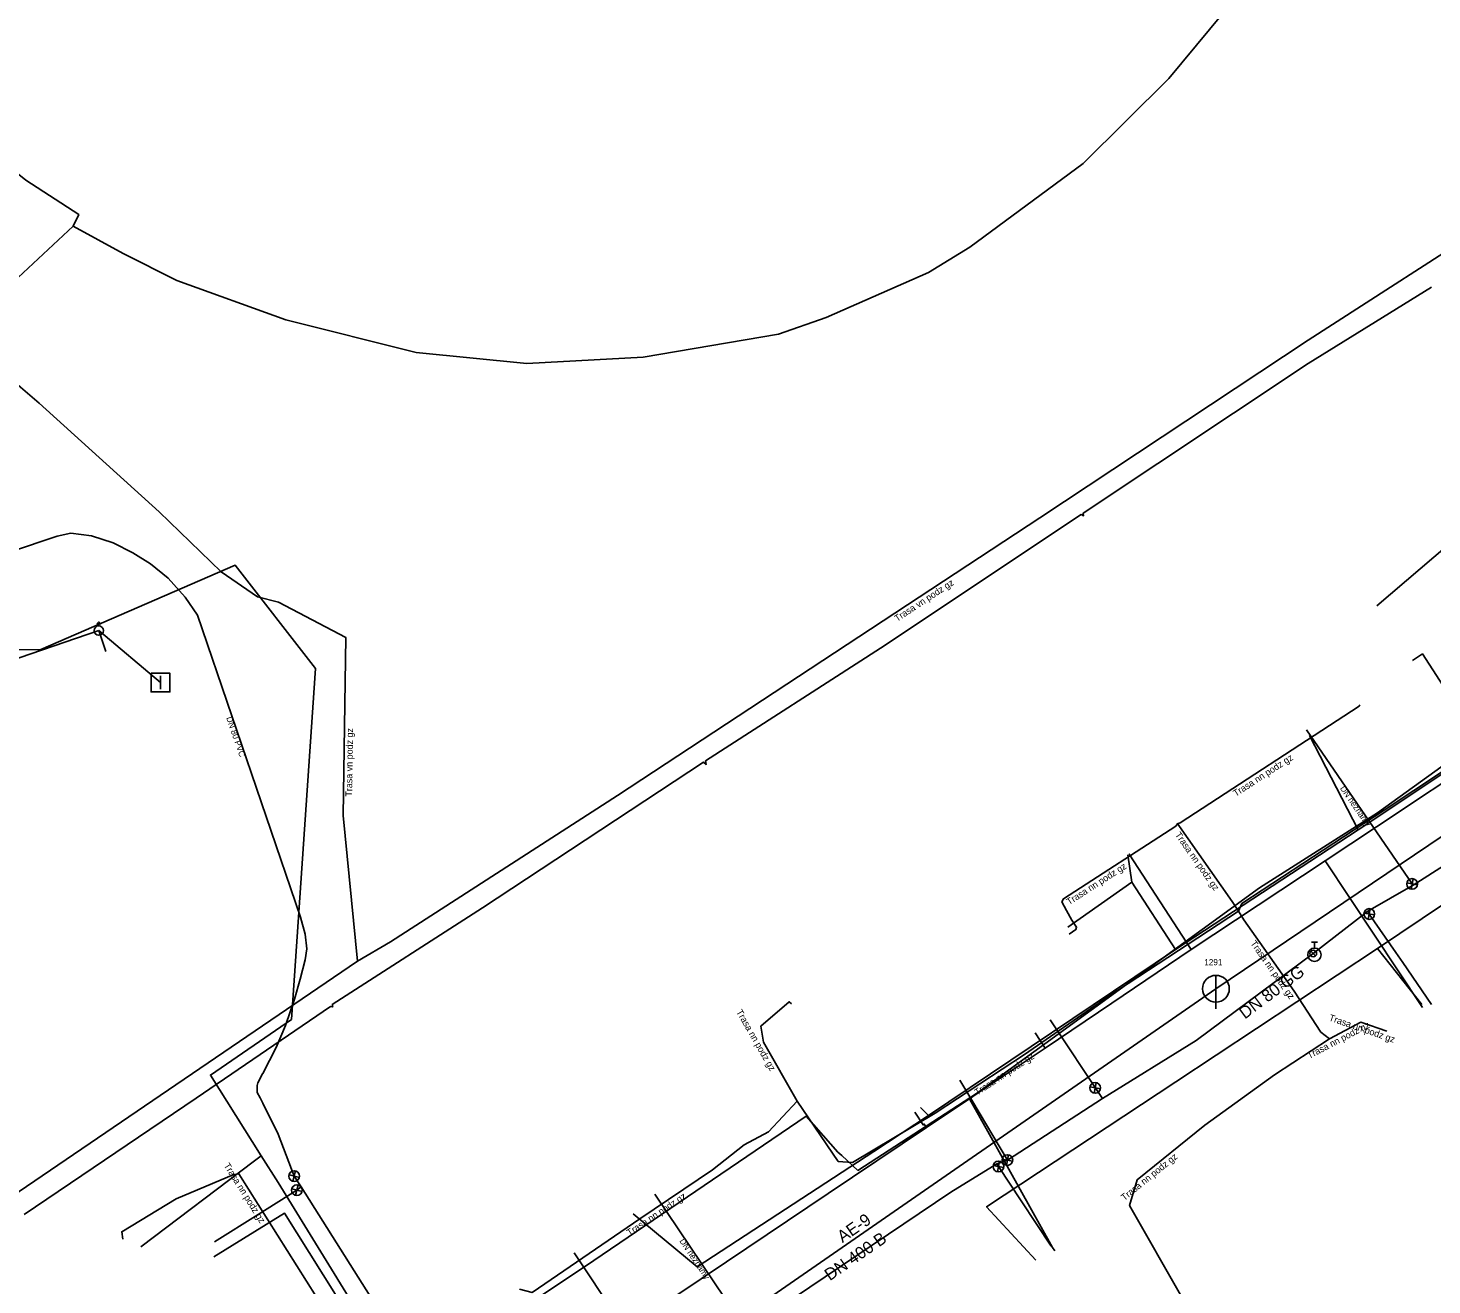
# Model space of a CAD drawing. Extents: x -493753 to -49291, y -1127285 to -112662.
# Drawn here: x -493093.4 to -492988.4, y -1126972.9 to -1126878.9 of the extents above; entities that cross this region are included whole.
import ezdxf

# ---------------------------------------------------------------- set-up
doc = ezdxf.new("R2010")
doc.units = 0
for name, color, linetype in [('Vrstva 1', 7, 'Continuous'), ('Vrstva 15', 7, 'Continuous'), ('Vrstva 17', 7, 'Continuous'), ('Vrstva 19', 7, 'Continuous'), ('Vrstva 20', 7, 'Continuous'), ('Vrstva 22', 7, 'Continuous'), ('Vrstva 24', 7, 'Continuous'), ('Vrstva 25', 7, 'Continuous'), ('Vrstva 26', 7, 'Continuous'), ('Vrstva 36', 7, 'Continuous'), ('Vrstva 39', 7, 'Continuous'), ('Vrstva 5', 7, 'Continuous'), ('Vrstva 6', 7, 'Continuous'), ('Vrstva 9', 7, 'Continuous')]:
    doc.layers.add(name, color=color, linetype=linetype)

# ---------------------------------------------------------------- blocks, each defined once
blk = doc.blocks.new('_UZAVE')
at = {"layer": 'Vrstva 1'}
for p, q in [((-0.035, -0.035), (0.035, 0.035)), ((0.035, -0.035), (-0.035, 0.035))]:
    blk.add_line(p, q, dxfattribs=at)
for radius in [0.05, 0.0025]:
    blk.add_circle((0, 0), radius, dxfattribs=at)
blk = doc.blocks.new('_UZAV0')
at = {"layer": 'Vrstva 1'}
for p, q in [((-0.035, -0.035), (0.035, 0.035)), ((0.035, -0.035), (-0.035, 0.035))]:
    blk.add_line(p, q, dxfattribs=at)
for radius in [0.05, 0.0025]:
    blk.add_circle((0, 0), radius, dxfattribs=at)
blk = doc.blocks.new('_HYDRA')
at = {"layer": 'Vrstva 1'}
for p, q in [((-0.0225, 0.095), (0.0225, 0.095)), ((0, 0.095), (0, 0.05))]:
    blk.add_line(p, q, dxfattribs=at)
blk.add_circle((0, 0), 0.05, dxfattribs=at)
blk = doc.blocks.new('_VPUST')
at = {"layer": 'Vrstva 1'}
blk.add_line((0, 0.025), (0, -0.025), dxfattribs=at)
blk.add_lwpolyline([(-0.035, 0.035), (0.035, 0.035), (0.035, -0.035), (-0.035, -0.035), (-0.035, 0.035)], dxfattribs=at)
blk = doc.blocks.new('_SACHT')
at = {"layer": 'Vrstva 1'}
blk.add_line((0, 0.035), (0, 0.05), dxfattribs=at)
blk.add_lwpolyline([(-0.015, 0.05), (0, 0.065), (0.015, 0.05), (0.0025, 0.05)], close=True, dxfattribs=at)
blk.add_circle((0, 0), 0.035, dxfattribs=at)
blk = doc.blocks.new('_SACH0')
at = {"layer": 'Vrstva 1'}
blk.add_line((0, 0.05), (0, -0.075), dxfattribs=at)
blk.add_circle((0, 0), 0.05, dxfattribs=at)

msp = doc.modelspace()

# ---------------------------------------------------------------- linework, layer by layer
at = {"layer": 'Vrstva 1'}
for p, q in [((-492989.07, -1126952.14), (-492996.36, -1126941.15)), ((-493018.05, -1126954.04), (-493017.3, -1126955.17)), ((-493076.44, -1126963.61), (-493075.92, -1126963.23)), ((-493076.44, -1126963.61), (-493084.94, -1126970.04)), ((-493052.53, -1126970.5), (-493048.7, -1126976.24))]:
    msp.add_line(p, q, dxfattribs=at)
for points in [[(-493061.95, -1126984.36), (-493055.3, -1126980.28), (-493048.7, -1126976.24), (-493041.12, -1126971.16), (-493033.53, -1126966.06), (-493026.17, -1126961.12), (-493022.95, -1126958.96), (-493022.37, -1126958.57), (-493017.3, -1126955.17), (-493012.3, -1126951.82), (-493006.38, -1126947.79), (-492996.36, -1126941.15), (-492992.52, -1126938.61), (-492984.26, -1126933.14), (-492976.86, -1126928.19), (-492969.03, -1126922.96), (-492962.21, -1126918.4), (-492958.1, -1126915.7), (-492957.92, -1126915.58), (-492957.82, -1126915.51), (-492938.13, -1126902.44)], [(-493075.92, -1126963.23), (-493079.73, -1126957.19), (-493073.66, -1126953.03), (-493071.87, -1126926.77), (-493077.88, -1126919.03), (-493092.4, -1126925.36), (-493094.9, -1126925.37)], [(-492984.26, -1126933.14), (-492989.08, -1126925.68), (-492989.83, -1126926.17)], [(-493011, -1126940.66), (-493011, -1126940.66), (-493006.38, -1126947.79)], [(-493016.58, -1126970.35), (-493016.75, -1126970.1), (-493019.17, -1126965.75), (-493021.59, -1126961.41), (-493022.95, -1126958.96)], [(-493026.17, -1126961.12), (-493026.34, -1126960.86), (-493026.42, -1126960.92), (-493027.04, -1126959.97)], [(-493075.92, -1126963.23), (-493074.66, -1126965.23), (-493065.8, -1126979.63), (-493063.11, -1126982.37), (-493061.95, -1126984.36), (-493057.28, -1126992.38), (-493056.62, -1126993.03), (-493050.57, -1126989.11), (-493043.53, -1127000), (-493040.17, -1127005.19), (-493038.27, -1127007.88), (-493030.16, -1127020.23)]]:
    msp.add_lwpolyline(points, dxfattribs=at)
at = {"layer": 'Vrstva 15'}
for p, q in [((-493088.08, -1126923.94), (-493098.62, -1126927.55)), ((-493087.54, -1126925.49), (-493088.08, -1126923.94)), ((-493083.46, -1126927.83), (-493088.08, -1126923.94)), ((-493057.41, -1126987.33), (-493004.52, -1126950.73))]:
    msp.add_line(p, q, dxfattribs=at)
msp.add_lwpolyline([(-493004.52, -1126950.73), (-492947.09, -1126911.99), (-492946.12, -1126911.1), (-492945.07, -1126909.77), (-492944.31, -1126908.4), (-492943.77, -1126906.95), (-492943.45, -1126905.36), (-492943.45, -1126904.13), (-492943.48, -1126903.21), (-492943.66, -1126901.96), (-492944.03, -1126900.73), (-492944.65, -1126899.35)], dxfattribs=at)
at = {"layer": 'Vrstva 20'}
for p, q in [((-492997.24, -1126948.09), (-492997.15, -1126948.19)), ((-492990.54, -1126948.78), (-492991.07, -1126948.01)), ((-492988.4, -1126951.9), (-492990.54, -1126948.78)), ((-493016.93, -1126953.07), (-493013.01, -1126958.95)), ((-493023.68, -1126957.57), (-493022.78, -1126959.08)), ((-493022.78, -1126959.08), (-493020.12, -1126963.55)), ((-493039.64, -1126976.26), (-493046.48, -1126966.09)), ((-493016.84, -1126970), (-493019.09, -1126966.61)), ((-493079.41, -1126969.66), (-493076.16, -1126967.62))]:
    msp.add_line(p, q, dxfattribs=at)
for points in [[(-493058.35, -1126988.86), (-493024.34, -1126965.95), (-493020.92, -1126963.84), (-493020.12, -1126963.55), (-493013.01, -1126958.95), (-493005.99, -1126954.61), (-492997.24, -1126948.09), (-492993.15, -1126944.92), (-492989.76, -1126942.99), (-492970.31, -1126930.58), (-492962.98, -1126925.47), (-492940.62, -1126910.81)], [(-493075.82, -1126957.1), (-493075.8, -1126957.08), (-493074.82, -1126955.14), (-493074.12, -1126953.49), (-493073.43, -1126951.51), (-493073.01, -1126950.02), (-493072.63, -1126948.56), (-493072.52, -1126947.74), (-493072.63, -1126946.66), (-493072.99, -1126945.37), (-493080.69, -1126922.79), (-493081.62, -1126921.43), (-493082.89, -1126920.01), (-493084.22, -1126918.93), (-493085.52, -1126918.12), (-493087, -1126917.38), (-493088.61, -1126916.85), (-493090.16, -1126916.64), (-493091.18, -1126916.88), (-493101.84, -1126920.45)], [(-492989.76, -1126942.99), (-492989.85, -1126942.89), (-492997.74, -1126931.37)], [(-492991.07, -1126948.01), (-492993.05, -1126945.14), (-492993.15, -1126944.92)], [(-493073.46, -1126964.75), (-493074.67, -1126961.6), (-493075.81, -1126959.29), (-493076.01, -1126958.9), (-493076.22, -1126958.49), (-493076.22, -1126958.22), (-493076.22, -1126957.98), (-493076.18, -1126957.76), (-493075.82, -1126957.1)], [(-493019.09, -1126966.61), (-493020.79, -1126964.03), (-493020.92, -1126963.84)], [(-493076.16, -1126967.62), (-493073.26, -1126965.8), (-493072.94, -1126965.55)], [(-493073.46, -1126964.75), (-493072.94, -1126965.55), (-493061.46, -1126983.73), (-493058.56, -1126988.53)]]:
    msp.add_lwpolyline(points, dxfattribs=at)
at = {"layer": 'Vrstva 25'}
msp.add_lwpolyline([(-493093.65, -1126967.62), (-493080.79, -1126958.93), (-493070.75, -1126952.05), (-493070.58, -1126952.09), (-493070.61, -1126951.91), (-493059.37, -1126944.69), (-493042.86, -1126933.79), (-493042.64, -1126933.95), (-493042.69, -1126933.69), (-493029.61, -1126925.25), (-493014.61, -1126915.26), (-493014.42, -1126915.34), (-493014.45, -1126915.14), (-492997.62, -1126903.95), (-492988.4, -1126898.25)], dxfattribs=at)
at = {"layer": 'Vrstva 26'}
for p, q in [((-492981.99, -1126930.04), (-492992.44, -1126937.56)), ((-492992.44, -1126937.56), (-493001.26, -1126943.19)), ((-493001.26, -1126943.19), (-493022.43, -1126958.57)), ((-493022.43, -1126958.57), (-493031.3, -1126964.34)), ((-493035.18, -1126960.26), (-493051.68, -1126971.48)), ((-493032.79, -1126962.96), (-493035.18, -1126960.26)), ((-493032.51, -1126963.2), (-493032.79, -1126962.96)), ((-493031.3, -1126964.34), (-493032.51, -1126963.2)), ((-493051.68, -1126971.48), (-493058.82, -1126976.24))]:
    msp.add_line(p, q, dxfattribs=at)
at = {"layer": 'Vrstva 36'}
msp.add_line((-492992.48, -1126922.08), (-492940.32, -1126877.38), dxfattribs=at)
at = {"layer": 'Vrstva 39'}
for points in [[(-493090, -1126893.68), (-493089.57, -1126892.81), (-493093.54, -1126890.23), (-493099.22, -1126885.65), (-493103.09, -1126881.61), (-493106.9, -1126876.5), (-493108.16, -1126874.25), (-493116.88, -1126869.66), (-493120.13, -1126868.36), (-493123.78, -1126862.9), (-493134.35, -1126847.08), (-493133.69, -1126846.76)], [(-493090, -1126893.68), (-493086.25, -1126895.72), (-493082.24, -1126897.74), (-493074.08, -1126900.68), (-493064.34, -1126903.13), (-493056.07, -1126903.96), (-493047.37, -1126903.49), (-493037.25, -1126901.75), (-493033.68, -1126900.51), (-493026.03, -1126897.15), (-493022.93, -1126895.26), (-493014.44, -1126889), (-493008.05, -1126882.62), (-493001.95, -1126875.27), (-492996.75, -1126867.41), (-492993.05, -1126859.65), (-492992.38, -1126855.25)], [(-493090, -1126893.68), (-493096.37, -1126899.62), (-493101.76, -1126903.61)], [(-492993.87, -1126938.84), (-492974.65, -1126926.06)], [(-492992.43, -1126947.71), (-492964.03, -1126928.65)], [(-492993.87, -1126938.84), (-492997.51, -1126931.79)], [(-492993.87, -1126938.84), (-493001.76, -1126944)], [(-493010.82, -1126942.75), (-493011.12, -1126940.72)], [(-493010.82, -1126942.75), (-493015.6, -1126946.12)], [(-493010.82, -1126942.75), (-493007.55, -1126947.79)], [(-493001.76, -1126944), (-493007.55, -1126947.79)], [(-493026.01, -1126960.22), (-493007.55, -1126947.79)], [(-492992.43, -1126947.71), (-493007.51, -1126957.69), (-493021.67, -1126967.04), (-493017.98, -1126971.03)], [(-492992.43, -1126947.71), (-492989.11, -1126951.92)], [(-493026.01, -1126960.22), (-493030.11, -1126962.9)], [(-493026.01, -1126960.22), (-493026.62, -1126959.62)], [(-493030.11, -1126962.9), (-493043.33, -1126971.54), (-493048.1, -1126967.58)], [(-493061.83, -1126987.26), (-493074.18, -1126967.53), (-493079.47, -1126970.79)]]:
    msp.add_lwpolyline(points, dxfattribs=at)
at = {"layer": 'Vrstva 5'}
for points in [[(-492968.17, -1126921.47), (-492971.15, -1126923.45), (-492980.93, -1126930.07), (-492991.95, -1126937.37), (-493002.59, -1126944.36), (-493002.84, -1126944.94)], [(-493007.4, -1126938.39), (-493007.19, -1126938.31), (-492993.8, -1126929.59), (-492993.77, -1126929.48)], [(-493002.84, -1126944.94), (-493003.3, -1126944.21), (-493007.43, -1126938.34)], [(-493007.4, -1126938.39), (-493007.52, -1126938.57), (-493015.93, -1126944), (-493016.04, -1126944.23), (-493015.7, -1126944.87), (-493015.29, -1126945.6), (-493014.94, -1126946.12), (-493015, -1126946.31), (-493015.49, -1126946.64)], [(-493002.84, -1126944.94), (-493012.6, -1126951.34), (-493018.85, -1126955.65), (-493025.53, -1126960.04), (-493031.7, -1126963.73), (-493032.77, -1126963.66), (-493035.84, -1126959.14)], [(-493002.84, -1126944.94), (-493002.43, -1126945.57), (-492998.67, -1126950.91), (-492996.67, -1126953.97), (-492996.03, -1126954.47)], [(-493035.84, -1126959.14), (-493038.37, -1126954.73), (-493038.55, -1126953.53), (-493036.43, -1126951.7), (-493036.26, -1126951.87)], [(-492996.03, -1126954.47), (-492993.68, -1126953.24), (-492993.62, -1126953.26)], [(-492993.62, -1126953.26), (-492991.74, -1126953.91)], [(-492996.03, -1126954.47), (-493000.14, -1126957.18), (-493005.36, -1126960.95), (-493010.42, -1126965.02), (-493010.98, -1126966.94), (-493006.97, -1126973.98), (-493010.17, -1126976.1), (-493010.66, -1126976.42)], [(-493035.84, -1126959.14), (-493037.99, -1126961.44), (-493039.81, -1126962.4), (-493042.17, -1126964.29), (-493047.62, -1126967.95), (-493055.67, -1126973.45), (-493056.61, -1126973.22)], [(-493069.65, -1126977.21), (-493077.59, -1126964.57), (-493077.98, -1126964.63), (-493082.28, -1126966.46), (-493086.36, -1126968.91), (-493086.27, -1126969.46)]]:
    msp.add_lwpolyline(points, dxfattribs=at)
at = {"layer": 'Vrstva 6'}
for points in [[(-493068.72, -1126948.66), (-493066.27, -1126947.23), (-493049.28, -1126936.27), (-493017.68, -1126915.5), (-492997.61, -1126902.22), (-492983.13, -1126892.87)], [(-493140.51, -1126905.23), (-493137.38, -1126905), (-493133.66, -1126905.28), (-493127.75, -1126903.34), (-493119.32, -1126900.41), (-493106.15, -1126895.75), (-493104.83, -1126895.77), (-493102.66, -1126897.52), (-493100.78, -1126899.84), (-493097.27, -1126902.88), (-493092.53, -1126906.92), (-493083.56, -1126915.04), (-493078.92, -1126919.55), (-493076.21, -1126921.42)], [(-493068.72, -1126948.66), (-493069.8, -1126937.76), (-493069.61, -1126924.45), (-493074.64, -1126921.81), (-493076.21, -1126921.42)], [(-493208.79, -1127019.8), (-493206.9, -1127018.9), (-493181.87, -1127010.51), (-493157.66, -1127002.21), (-493137.92, -1126995.41), (-493124.01, -1126986.08), (-493102.33, -1126971.53), (-493068.72, -1126948.66)]]:
    msp.add_lwpolyline(points, dxfattribs=at)

# ---------------------------------------------------------------- block references
at = {"layer": 'Vrstva 17'}
for name, p, xscale, yscale in [('_SACHT', (-493088.08, -1126923.94), 9.998750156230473, 9.998750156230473), ('_VPUST', (-493083.46, -1126927.83), 19.997500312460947, 19.997500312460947), ('_SACH0', (-493004.52, -1126950.73), 19.997500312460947, 19.997500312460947)]:
    msp.add_blockref(name, p, dxfattribs=dict(at, xscale=xscale, yscale=yscale))
at = {"layer": 'Vrstva 22'}
for p, xscale, yscale, rotation in [((-492989.85, -1126942.89), 7.999000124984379, 7.999000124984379, -55.332352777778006), ((-492993.05, -1126945.14), 7.999000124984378, 7.999000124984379, 34.387877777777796), ((-493013.55, -1126958.15), 7.999000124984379, 7.99900012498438, 33.632347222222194), ((-493020.79, -1126964.03), 7.999000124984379, 7.999000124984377, -146.50232777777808), ((-493020.12, -1126963.55), 7.999000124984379, 7.999000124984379, 33.72114722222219), ((-493073.46, -1126964.75), 7.999000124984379, 7.999000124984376, -58.85639722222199), ((-493073.26, -1126965.8), 7.99900012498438, 7.999000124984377, -58.62077222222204)]:
    msp.add_blockref('_UZAV0', p, dxfattribs=dict(at, xscale=xscale, yscale=yscale, rotation=rotation))
for name, p, xscale, yscale in [('_HYDRA', (-492997.15, -1126948.19), 9.998750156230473, 9.998750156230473), ('_UZAVE', (-492997.24, -1126948.09), 4.999375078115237, 4.999375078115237)]:
    msp.add_blockref(name, p, dxfattribs=dict(at, xscale=xscale, yscale=yscale))

# ---------------------------------------------------------------- texts
at = {"layer": 'Vrstva 19'}
msp.add_text('1291', height=0.455, dxfattribs=at).set_placement((-493005.39, -1126948.97))
for s, p in [('AE-9', (-493032.45, -1126969.77)), ('DN 400 B', (-493033.4, -1126972.62))]:
    msp.add_text(s, height=0.91, rotation=34.6778, dxfattribs=at).set_placement(p)
at = {"layer": 'Vrstva 24'}
for s, height, rotation, p in [('DN 80 PVC', 0.455, 288.8336, (-493078.55, -1126930.46)), ('DN neznámý', 0.455, 304.4058, (-492995.26, -1126935.74)), ('DN 80 GG', 0.91, 36.7113, (-493002.36, -1126953.04)), ('DN neznámý', 0.455, 303.9209, (-493044.67, -1126969.61))]:
    msp.add_text(s, height=height, rotation=rotation, dxfattribs=at).set_placement(p)
at = {"layer": 'Vrstva 9'}
for s, rotation, p in [('Trasa vn podz gz', 33.3161, (-493028.36, -1126923.29)), ('Trasa vn podz gz', 89.1822, (-493069.13, -1126936.36)), ('Trasa nn podz gz', 33.0804, (-493003.03, -1126936.38)), ('Trasa nn podz gz', 305.1274, (-493007.61, -1126939.22)), ('Trasa nn podz gz', 32.8174, (-493015.5, -1126944.49)), ('Trasa nn podz gz', 305.1265, (-493001.97, -1126947.34)), ('Trasa nn podz gz', 299.8371, (-493040.42, -1126952.46)), ('Trasa nn podz gz', 341.0113, (-492996.11, -1126953.1)), ('Trasa nn podz gz', 27.5403, (-492997.54, -1126955.99)), ('Trasa nn podz gz', 33.2904, (-493022.37, -1126958.74)), ('Trasa nn podz gz', 38.8391, (-493011.37, -1126966.62)), ('Trasa nn podz gz', 302.1405, (-493078.75, -1126963.96)), ('Trasa nn podz gz', 33.9079, (-493048.38, -1126969.25))]:
    msp.add_text(s, height=0.5, rotation=rotation, dxfattribs=at).set_placement(p)

doc.saveas('drawing.dxf')
